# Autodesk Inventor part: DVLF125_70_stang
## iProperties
Created: 2010-04
Part Number: DVLF125_70_stang
Document SubType Name: Modeling
Designer: TB
Mass: 1487.97 g
Surface Area: 928.867 cm^2
Volume: 1487.97 cm^3
Density: 1 g/cm^3
Author: TB
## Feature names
1. Revolution1
2. Fillet1
3. Revolution2
